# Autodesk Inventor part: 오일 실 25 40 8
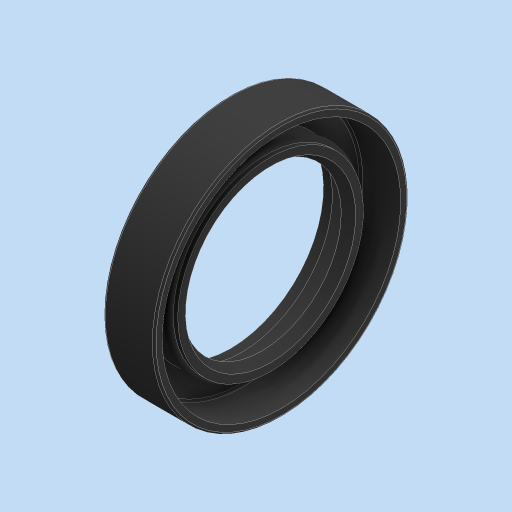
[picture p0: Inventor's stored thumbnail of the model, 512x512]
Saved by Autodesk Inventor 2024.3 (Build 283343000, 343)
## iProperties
Created: 2025-11
Part Number: 오일 실 25 40 8
Material: 고무
Description: 오일-실
Document SubType Name: Modeling
Designer: PC2-02
Density: 0.93 g/cm^3
Appearance: 기본값
Author: jhkim
Sending System: Autodesk Inventor 2026
Preprocessor: ST-DEVELOPER v20.1
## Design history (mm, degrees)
node "오일 실 25 40 81"
node "솔리드1"
body "Solid1"
